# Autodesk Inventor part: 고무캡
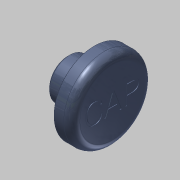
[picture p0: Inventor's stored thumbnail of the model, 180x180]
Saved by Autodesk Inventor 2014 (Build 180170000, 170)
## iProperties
Created: 2017-06
Part Number: 고무캡
Material: 고무
Document SubType Name: Modeling
Designer: mduedu
Density: 1 g/cm^3
Appearance: 고무 - 파란색 - 버전 1.1
Author: mduedu
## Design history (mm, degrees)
sketch "스케치1"
  geometry: L1 (0, 0)-(11, 0); L2 (11, 0)-(11, 10); L3 (11, 10)-(6.5, 10); L4 (0, 5)-(0, 0); L5 (0, 5)-(6, 5); L6 (6, 5)-(6, 9); L7 (6, 9)-(6.5, 9); L8 (6.5, 9)-(6.5, 10)
  constraints: 16 end point, 2 horizontal, 2 parallel, 2 perpendicular, 2 point on line, 1 vertical
  dimensions: "d0" = 20 diameter of L3 L1; "d2" = 10 diameter of L5 L1; "d6" = 5 distance between parallel lines of L2 L6; "d7" = 0.5 distance between parallel lines of L8 L6; "d8" = 18 diameter of L7 L1; "d9" = 6 distance between parallel lines of L6 L4
revolve "회전1" sketch "스케치1" stored, may be unused: angle "d10" = 90 deg
hole "구멍1" diameter "d22" = 7; stored, may be unused: countersink angle "d26" = 90 deg, drill point angle "d28" = 0 deg; dims "d23" = 6, "d24" = 4, "d25" = 2, "d27" = 6, "d32" = 10, "d33" = 10
chamfer "모따기1" distance "d13" = 0.5; stored, may be unused: second distance "d14" = 2, angle "d15" = 45 deg
fillet "모깎기3" dims "d29" = 1
fillet "모깎기1" dims "d16" = 0.1
fillet "모깎기2" dims "d17" = 2
sketch "스케치3"
  geometry: 2 further points
  constraints: 1 coincident, 1 other
feature "엠보싱1" sketch "스케치3" dims "d18" = 0.2, "d19" = 0
node "솔리드1"
